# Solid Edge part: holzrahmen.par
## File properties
Author: Susi
Template: Normal.par
Last saved by: Susi
Revision: 1
Application: Solid Edge
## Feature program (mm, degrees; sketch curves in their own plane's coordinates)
sketch for "unnamed Protrusion 1" plane through (0, 0, 0) normal (0, 0, 1) x-axis (1, 0, 0)
extrude "unnamed Protrusion 1" add finite 20 along +normal
sketch for "unnamed Cutout 1" plane through (-41.6667, 35.8, 20) normal (0, 0, 1) x-axis (0, 1, 0)
extrude "unnamed Cutout 1" cut finite 10 along -normal
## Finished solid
Body 1: solid body, 11 faces, 24 edges, 16 vertices.
  Faces by surface: plane 11
  Edges by curve: line 24
Bounding box of the edges (mm): 120.000 x 120.000 x 20.000, from (-101.6667, -24.2, 0) to (18.3333, 95.8, 20).
Planar faces by outward normal: +x 2, +y 2, +z 2, -x 2, -y 2, -z 1
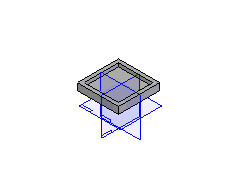
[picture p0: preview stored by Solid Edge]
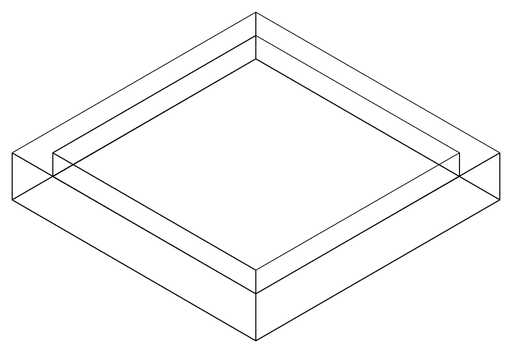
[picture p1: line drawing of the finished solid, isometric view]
